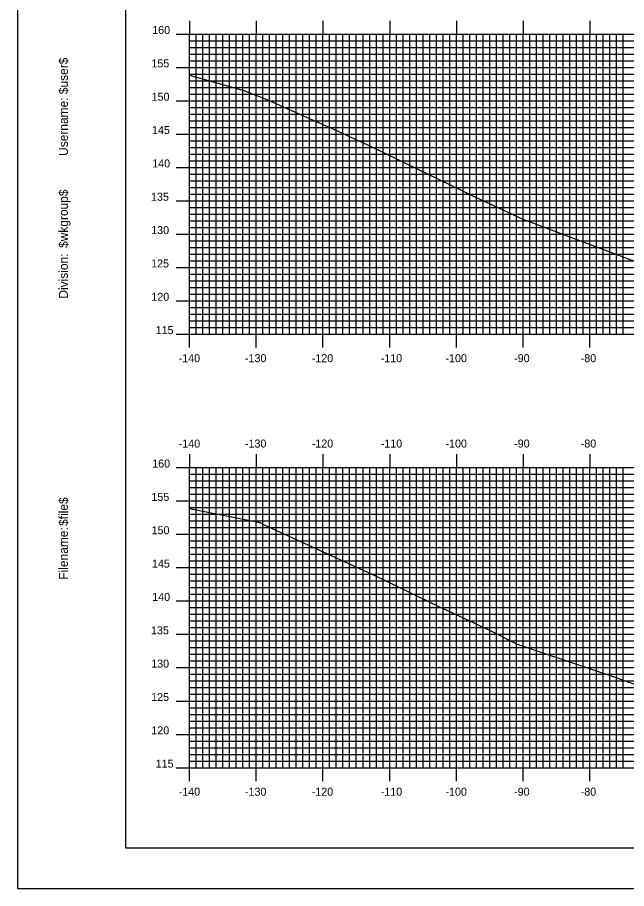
# Model space of a CAD drawing. Extents: x 851139 to 851482, y 366605 to 366825.
# Drawn here: x 851139.2 to 851230.4, y 366604.9 to 366735.5 of the extents above; entities that cross this region are included whole.
import ezdxf

# ---------------------------------------------------------------- set-up
doc = ezdxf.new("R2010")
doc.units = 0
for name, color, linetype in [('BORDER', 7, 'Continuous'), ('H_V ANNOTATION', 7, 'Continuous'), ('MAJOR', 7, 'Continuous'), ('MINOR', 7, 'Continuous'), ('PLOT BOUNDARY', 7, 'Continuous'), ('S_Roadway_Centerline', 7, 'Continuous')]:
    doc.layers.add(name, color=color, linetype=linetype)

msp = doc.modelspace()

# ---------------------------------------------------------------- linework, layer by layer
at = {"layer": 'BORDER'}
msp.add_lwpolyline([(851155.34, 366611.06), (851475.34, 366611.06), (851475.34, 366821.06), (851155.34, 366821.06)], close=True, dxfattribs=at)
at = {"layer": 'MAJOR'}
for p, q in [((851164.94, 366735.06), (851164.94, 366733.06)), ((851174.94, 366735.06), (851174.94, 366733.06)), ((851184.94, 366735.06), (851184.94, 366733.06)), ((851194.94, 366735.06), (851194.94, 366733.06)), ((851204.94, 366735.06), (851204.94, 366733.06)), ((851214.94, 366735.06), (851214.94, 366733.06)), ((851224.94, 366735.06), (851224.94, 366733.06)), ((851162.93, 366733.06), (851164.94, 366733.06)), ((851164.94, 366733.06), (851444.94, 366733.06)), ((851164.94, 366688.06), (851164.94, 366733.06)), ((851164.94, 366688.06), (851164.94, 366733.06)), ((851164.94, 366733.06), (851444.94, 366733.06)), ((851174.94, 366688.06), (851174.94, 366733.06)), ((851184.94, 366688.06), (851184.94, 366733.06)), ((851194.94, 366688.06), (851194.94, 366733.06)), ((851204.94, 366688.06), (851204.94, 366733.06)), ((851214.94, 366688.06), (851214.94, 366733.06)), ((851224.94, 366688.06), (851224.94, 366733.06)), ((851162.93, 366728.06), (851164.94, 366728.06)), ((851164.94, 366728.06), (851444.94, 366728.06)), ((851162.93, 366723.06), (851164.94, 366723.06)), ((851164.94, 366723.06), (851444.94, 366723.06)), ((851162.93, 366718.06), (851164.94, 366718.06)), ((851164.94, 366718.06), (851444.94, 366718.06)), ((851162.93, 366713.06), (851164.94, 366713.06)), ((851164.94, 366713.06), (851444.94, 366713.06)), ((851162.93, 366708.06), (851164.94, 366708.06)), ((851164.94, 366708.06), (851444.94, 366708.06)), ((851162.93, 366703.06), (851164.94, 366703.06)), ((851164.94, 366703.06), (851444.94, 366703.06)), ((851162.93, 366698.06), (851164.94, 366698.06)), ((851164.94, 366698.06), (851444.94, 366698.06)), ((851162.93, 366693.06), (851164.94, 366693.06)), ((851164.94, 366693.06), (851444.94, 366693.06)), ((851162.93, 366688.06), (851164.94, 366688.06)), ((851164.94, 366688.06), (851444.94, 366688.06)), ((851164.94, 366688.06), (851444.94, 366688.06)), ((851164.94, 366686.05), (851164.94, 366688.06)), ((851174.94, 366686.05), (851174.94, 366688.06)), ((851184.94, 366686.05), (851184.94, 366688.06)), ((851194.94, 366686.05), (851194.94, 366688.06)), ((851204.94, 366686.05), (851204.94, 366688.06)), ((851214.94, 366686.05), (851214.94, 366688.06)), ((851224.94, 366686.05), (851224.94, 366688.06)), ((851164.94, 366670.06), (851164.94, 366668.06)), ((851174.94, 366670.06), (851174.94, 366668.06)), ((851184.94, 366670.06), (851184.94, 366668.06)), ((851194.94, 366670.06), (851194.94, 366668.06)), ((851204.94, 366670.06), (851204.94, 366668.06)), ((851214.94, 366670.06), (851214.94, 366668.06)), ((851224.94, 366670.06), (851224.94, 366668.06)), ((851162.93, 366668.06), (851164.94, 366668.06)), ((851164.94, 366668.06), (851444.94, 366668.06)), ((851164.94, 366623.06), (851164.94, 366668.06)), ((851164.94, 366623.06), (851164.94, 366668.06)), ((851164.94, 366668.06), (851444.94, 366668.06)), ((851174.94, 366623.06), (851174.94, 366668.06)), ((851184.94, 366623.06), (851184.94, 366668.06)), ((851194.94, 366623.06), (851194.94, 366668.06)), ((851204.94, 366623.06), (851204.94, 366668.06)), ((851214.94, 366623.06), (851214.94, 366668.06)), ((851224.94, 366623.06), (851224.94, 366668.06)), ((851162.93, 366663.06), (851164.94, 366663.06)), ((851164.94, 366663.06), (851444.94, 366663.06)), ((851162.93, 366658.06), (851164.94, 366658.06)), ((851164.94, 366658.06), (851444.94, 366658.06)), ((851162.93, 366653.06), (851164.94, 366653.06)), ((851164.94, 366653.06), (851444.94, 366653.06)), ((851162.93, 366648.06), (851164.94, 366648.06)), ((851164.94, 366648.06), (851444.94, 366648.06)), ((851162.93, 366643.06), (851164.94, 366643.06)), ((851164.94, 366643.06), (851444.94, 366643.06)), ((851162.93, 366638.06), (851164.94, 366638.06)), ((851164.94, 366638.06), (851444.94, 366638.06)), ((851162.93, 366633.06), (851164.94, 366633.06)), ((851164.94, 366633.06), (851444.94, 366633.06)), ((851162.93, 366628.06), (851164.94, 366628.06)), ((851164.94, 366628.06), (851444.94, 366628.06)), ((851162.93, 366623.06), (851164.94, 366623.06)), ((851164.94, 366623.06), (851444.94, 366623.06)), ((851164.94, 366623.06), (851444.94, 366623.06)), ((851164.94, 366621.05), (851164.94, 366623.06)), ((851174.94, 366621.05), (851174.94, 366623.06)), ((851184.94, 366621.05), (851184.94, 366623.06)), ((851194.94, 366621.05), (851194.94, 366623.06)), ((851204.94, 366621.05), (851204.94, 366623.06)), ((851214.94, 366621.05), (851214.94, 366623.06)), ((851224.94, 366621.05), (851224.94, 366623.06))]:
    msp.add_line(p, q, dxfattribs=at)
at = {"layer": 'MINOR'}
for p, q in [((851165.94, 366688.06), (851165.94, 366733.06)), ((851166.94, 366688.06), (851166.94, 366733.06)), ((851167.94, 366688.06), (851167.94, 366733.06)), ((851168.94, 366688.06), (851168.94, 366733.06)), ((851169.94, 366688.06), (851169.94, 366733.06)), ((851170.94, 366688.06), (851170.94, 366733.06)), ((851171.94, 366688.06), (851171.94, 366733.06)), ((851172.94, 366688.06), (851172.94, 366733.06)), ((851173.94, 366688.06), (851173.94, 366733.06)), ((851175.94, 366688.06), (851175.94, 366733.06)), ((851176.94, 366688.06), (851176.94, 366733.06)), ((851177.94, 366688.06), (851177.94, 366733.06)), ((851178.94, 366688.06), (851178.94, 366733.06)), ((851179.94, 366688.06), (851179.94, 366733.06)), ((851180.94, 366688.06), (851180.94, 366733.06)), ((851181.94, 366688.06), (851181.94, 366733.06)), ((851182.94, 366688.06), (851182.94, 366733.06)), ((851183.94, 366688.06), (851183.94, 366733.06)), ((851185.94, 366688.06), (851185.94, 366733.06)), ((851186.94, 366688.06), (851186.94, 366733.06)), ((851187.94, 366688.06), (851187.94, 366733.06)), ((851188.94, 366688.06), (851188.94, 366733.06)), ((851189.94, 366688.06), (851189.94, 366733.06)), ((851190.94, 366688.06), (851190.94, 366733.06)), ((851191.94, 366688.06), (851191.94, 366733.06)), ((851192.94, 366688.06), (851192.94, 366733.06)), ((851193.94, 366688.06), (851193.94, 366733.06)), ((851195.94, 366688.06), (851195.94, 366733.06)), ((851196.94, 366688.06), (851196.94, 366733.06)), ((851197.94, 366688.06), (851197.94, 366733.06)), ((851198.94, 366688.06), (851198.94, 366733.06)), ((851199.94, 366688.06), (851199.94, 366733.06)), ((851200.94, 366688.06), (851200.94, 366733.06)), ((851201.94, 366688.06), (851201.94, 366733.06)), ((851202.94, 366688.06), (851202.94, 366733.06)), ((851203.94, 366688.06), (851203.94, 366733.06)), ((851205.94, 366688.06), (851205.94, 366733.06)), ((851206.94, 366688.06), (851206.94, 366733.06)), ((851207.94, 366688.06), (851207.94, 366733.06)), ((851208.94, 366688.06), (851208.94, 366733.06)), ((851209.94, 366688.06), (851209.94, 366733.06)), ((851210.94, 366688.06), (851210.94, 366733.06)), ((851211.94, 366688.06), (851211.94, 366733.06)), ((851212.94, 366688.06), (851212.94, 366733.06)), ((851213.94, 366688.06), (851213.94, 366733.06)), ((851215.94, 366688.06), (851215.94, 366733.06)), ((851216.94, 366688.06), (851216.94, 366733.06)), ((851217.94, 366688.06), (851217.94, 366733.06)), ((851218.94, 366688.06), (851218.94, 366733.06)), ((851219.94, 366688.06), (851219.94, 366733.06)), ((851220.94, 366688.06), (851220.94, 366733.06)), ((851221.94, 366688.06), (851221.94, 366733.06)), ((851222.94, 366688.06), (851222.94, 366733.06)), ((851223.94, 366688.06), (851223.94, 366733.06)), ((851225.94, 366688.06), (851225.94, 366733.06)), ((851226.94, 366688.06), (851226.94, 366733.06)), ((851227.94, 366688.06), (851227.94, 366733.06)), ((851228.94, 366688.06), (851228.94, 366733.06)), ((851229.94, 366688.06), (851229.94, 366733.06)), ((851164.94, 366732.06), (851444.94, 366732.06)), ((851164.94, 366732.06), (851166.94, 366732.06)), ((851164.94, 366731.06), (851444.94, 366731.06)), ((851164.94, 366731.06), (851166.94, 366731.06)), ((851164.94, 366730.06), (851444.94, 366730.06)), ((851164.94, 366730.06), (851166.94, 366730.06)), ((851164.94, 366729.06), (851444.94, 366729.06)), ((851164.94, 366729.06), (851166.94, 366729.06)), ((851164.94, 366727.06), (851444.94, 366727.06)), ((851164.94, 366727.06), (851166.94, 366727.06)), ((851164.94, 366726.06), (851444.94, 366726.06)), ((851164.94, 366726.06), (851166.94, 366726.06)), ((851164.94, 366725.06), (851444.94, 366725.06)), ((851164.94, 366725.06), (851166.94, 366725.06)), ((851164.94, 366724.06), (851444.94, 366724.06)), ((851164.94, 366724.06), (851166.94, 366724.06)), ((851164.94, 366722.06), (851444.94, 366722.06)), ((851164.94, 366722.06), (851166.94, 366722.06)), ((851164.94, 366721.06), (851444.94, 366721.06)), ((851164.94, 366721.06), (851166.94, 366721.06)), ((851164.94, 366720.06), (851444.94, 366720.06)), ((851164.94, 366720.06), (851166.94, 366720.06)), ((851164.94, 366719.06), (851444.94, 366719.06)), ((851164.94, 366719.06), (851166.94, 366719.06)), ((851164.94, 366717.06), (851444.94, 366717.06)), ((851164.94, 366717.06), (851166.94, 366717.06)), ((851164.94, 366716.06), (851444.94, 366716.06)), ((851164.94, 366716.06), (851166.94, 366716.06)), ((851164.94, 366715.06), (851444.94, 366715.06)), ((851164.94, 366715.06), (851166.94, 366715.06)), ((851164.94, 366714.06), (851444.94, 366714.06)), ((851164.94, 366714.06), (851166.94, 366714.06)), ((851164.94, 366712.06), (851444.94, 366712.06)), ((851164.94, 366712.06), (851166.94, 366712.06)), ((851164.94, 366711.06), (851444.94, 366711.06)), ((851164.94, 366711.06), (851166.94, 366711.06)), ((851164.94, 366710.06), (851444.94, 366710.06)), ((851164.94, 366710.06), (851166.94, 366710.06)), ((851164.94, 366709.06), (851444.94, 366709.06)), ((851164.94, 366709.06), (851166.94, 366709.06)), ((851164.94, 366707.06), (851444.94, 366707.06)), ((851164.94, 366707.06), (851166.94, 366707.06)), ((851164.94, 366706.06), (851444.94, 366706.06)), ((851164.94, 366706.06), (851166.94, 366706.06)), ((851164.94, 366705.06), (851444.94, 366705.06)), ((851164.94, 366705.06), (851166.94, 366705.06)), ((851164.94, 366704.06), (851444.94, 366704.06)), ((851164.94, 366704.06), (851166.94, 366704.06)), ((851164.94, 366702.06), (851444.94, 366702.06)), ((851164.94, 366702.06), (851166.94, 366702.06)), ((851164.94, 366701.06), (851444.94, 366701.06)), ((851164.94, 366701.06), (851166.94, 366701.06)), ((851164.94, 366700.06), (851444.94, 366700.06)), ((851164.94, 366700.06), (851166.94, 366700.06)), ((851164.94, 366699.06), (851444.94, 366699.06)), ((851164.94, 366699.06), (851166.94, 366699.06)), ((851164.94, 366697.06), (851444.94, 366697.06)), ((851164.94, 366697.06), (851166.94, 366697.06)), ((851164.94, 366696.06), (851444.94, 366696.06)), ((851164.94, 366696.06), (851166.94, 366696.06)), ((851164.94, 366695.06), (851444.94, 366695.06)), ((851164.94, 366695.06), (851166.94, 366695.06)), ((851164.94, 366694.06), (851444.94, 366694.06)), ((851164.94, 366694.06), (851166.94, 366694.06)), ((851164.94, 366692.06), (851444.94, 366692.06)), ((851164.94, 366692.06), (851166.94, 366692.06)), ((851164.94, 366691.06), (851444.94, 366691.06)), ((851164.94, 366691.06), (851166.94, 366691.06)), ((851164.94, 366690.06), (851444.94, 366690.06)), ((851164.94, 366690.06), (851166.94, 366690.06)), ((851164.94, 366689.06), (851444.94, 366689.06)), ((851164.94, 366689.06), (851166.94, 366689.06)), ((851165.94, 366623.06), (851165.94, 366668.06)), ((851166.94, 366623.06), (851166.94, 366668.06)), ((851167.94, 366623.06), (851167.94, 366668.06)), ((851168.94, 366623.06), (851168.94, 366668.06)), ((851169.94, 366623.06), (851169.94, 366668.06)), ((851170.94, 366623.06), (851170.94, 366668.06)), ((851171.94, 366623.06), (851171.94, 366668.06)), ((851172.94, 366623.06), (851172.94, 366668.06)), ((851173.94, 366623.06), (851173.94, 366668.06)), ((851175.94, 366623.06), (851175.94, 366668.06)), ((851176.94, 366623.06), (851176.94, 366668.06)), ((851177.94, 366623.06), (851177.94, 366668.06)), ((851178.94, 366623.06), (851178.94, 366668.06)), ((851179.94, 366623.06), (851179.94, 366668.06)), ((851180.94, 366623.06), (851180.94, 366668.06)), ((851181.94, 366623.06), (851181.94, 366668.06)), ((851182.94, 366623.06), (851182.94, 366668.06)), ((851183.94, 366623.06), (851183.94, 366668.06)), ((851185.94, 366623.06), (851185.94, 366668.06)), ((851186.94, 366623.06), (851186.94, 366668.06)), ((851187.94, 366623.06), (851187.94, 366668.06)), ((851188.94, 366623.06), (851188.94, 366668.06)), ((851189.94, 366623.06), (851189.94, 366668.06)), ((851190.94, 366623.06), (851190.94, 366668.06)), ((851191.94, 366623.06), (851191.94, 366668.06)), ((851192.94, 366623.06), (851192.94, 366668.06)), ((851193.94, 366623.06), (851193.94, 366668.06)), ((851195.94, 366623.06), (851195.94, 366668.06)), ((851196.94, 366623.06), (851196.94, 366668.06)), ((851197.94, 366623.06), (851197.94, 366668.06)), ((851198.94, 366623.06), (851198.94, 366668.06)), ((851199.94, 366623.06), (851199.94, 366668.06)), ((851200.94, 366623.06), (851200.94, 366668.06)), ((851201.94, 366623.06), (851201.94, 366668.06)), ((851202.94, 366623.06), (851202.94, 366668.06)), ((851203.94, 366623.06), (851203.94, 366668.06)), ((851205.94, 366623.06), (851205.94, 366668.06)), ((851206.94, 366623.06), (851206.94, 366668.06)), ((851207.94, 366623.06), (851207.94, 366668.06)), ((851208.94, 366623.06), (851208.94, 366668.06)), ((851209.94, 366623.06), (851209.94, 366668.06)), ((851210.94, 366623.06), (851210.94, 366668.06)), ((851211.94, 366623.06), (851211.94, 366668.06)), ((851212.94, 366623.06), (851212.94, 366668.06)), ((851213.94, 366623.06), (851213.94, 366668.06)), ((851215.94, 366623.06), (851215.94, 366668.06)), ((851216.94, 366623.06), (851216.94, 366668.06)), ((851217.94, 366623.06), (851217.94, 366668.06)), ((851218.94, 366623.06), (851218.94, 366668.06)), ((851219.94, 366623.06), (851219.94, 366668.06)), ((851220.94, 366623.06), (851220.94, 366668.06)), ((851221.94, 366623.06), (851221.94, 366668.06)), ((851222.94, 366623.06), (851222.94, 366668.06)), ((851223.94, 366623.06), (851223.94, 366668.06)), ((851225.94, 366623.06), (851225.94, 366668.06)), ((851226.94, 366623.06), (851226.94, 366668.06)), ((851227.94, 366623.06), (851227.94, 366668.06)), ((851228.94, 366623.06), (851228.94, 366668.06)), ((851229.94, 366623.06), (851229.94, 366668.06)), ((851164.94, 366667.06), (851444.94, 366667.06)), ((851164.94, 366667.06), (851166.94, 366667.06)), ((851164.94, 366666.06), (851444.94, 366666.06)), ((851164.94, 366666.06), (851166.94, 366666.06)), ((851164.94, 366665.06), (851444.94, 366665.06)), ((851164.94, 366665.06), (851166.94, 366665.06)), ((851164.94, 366664.06), (851444.94, 366664.06)), ((851164.94, 366664.06), (851166.94, 366664.06)), ((851164.94, 366662.06), (851444.94, 366662.06)), ((851164.94, 366662.06), (851166.94, 366662.06)), ((851164.94, 366661.06), (851444.94, 366661.06)), ((851164.94, 366661.06), (851166.94, 366661.06)), ((851164.94, 366660.06), (851444.94, 366660.06)), ((851164.94, 366660.06), (851166.94, 366660.06)), ((851164.94, 366659.06), (851444.94, 366659.06)), ((851164.94, 366659.06), (851166.94, 366659.06)), ((851164.94, 366657.06), (851444.94, 366657.06)), ((851164.94, 366657.06), (851166.94, 366657.06)), ((851164.94, 366656.06), (851444.94, 366656.06)), ((851164.94, 366656.06), (851166.94, 366656.06)), ((851164.94, 366655.06), (851444.94, 366655.06)), ((851164.94, 366655.06), (851166.94, 366655.06)), ((851164.94, 366654.06), (851444.94, 366654.06)), ((851164.94, 366654.06), (851166.94, 366654.06)), ((851164.94, 366652.06), (851444.94, 366652.06)), ((851164.94, 366652.06), (851166.94, 366652.06)), ((851164.94, 366651.06), (851444.94, 366651.06)), ((851164.94, 366651.06), (851166.94, 366651.06)), ((851164.94, 366650.06), (851444.94, 366650.06)), ((851164.94, 366650.06), (851166.94, 366650.06)), ((851164.94, 366649.06), (851444.94, 366649.06)), ((851164.94, 366649.06), (851166.94, 366649.06)), ((851164.94, 366647.06), (851444.94, 366647.06)), ((851164.94, 366647.06), (851166.94, 366647.06)), ((851164.94, 366646.06), (851444.94, 366646.06)), ((851164.94, 366646.06), (851166.94, 366646.06)), ((851164.94, 366645.06), (851444.94, 366645.06)), ((851164.94, 366645.06), (851166.94, 366645.06)), ((851164.94, 366644.06), (851444.94, 366644.06)), ((851164.94, 366644.06), (851166.94, 366644.06)), ((851164.94, 366642.06), (851444.94, 366642.06)), ((851164.94, 366642.06), (851166.94, 366642.06)), ((851164.94, 366641.06), (851444.94, 366641.06)), ((851164.94, 366641.06), (851166.94, 366641.06)), ((851164.94, 366640.06), (851444.94, 366640.06)), ((851164.94, 366640.06), (851166.94, 366640.06)), ((851164.94, 366639.06), (851444.94, 366639.06)), ((851164.94, 366639.06), (851166.94, 366639.06)), ((851164.94, 366637.06), (851444.94, 366637.06)), ((851164.94, 366637.06), (851166.94, 366637.06)), ((851164.94, 366636.06), (851444.94, 366636.06)), ((851164.94, 366636.06), (851166.94, 366636.06)), ((851164.94, 366635.06), (851444.94, 366635.06)), ((851164.94, 366635.06), (851166.94, 366635.06)), ((851164.94, 366634.06), (851444.94, 366634.06)), ((851164.94, 366634.06), (851166.94, 366634.06)), ((851164.94, 366632.06), (851444.94, 366632.06)), ((851164.94, 366632.06), (851166.94, 366632.06)), ((851164.94, 366631.06), (851444.94, 366631.06)), ((851164.94, 366631.06), (851166.94, 366631.06)), ((851164.94, 366630.06), (851444.94, 366630.06)), ((851164.94, 366630.06), (851166.94, 366630.06)), ((851164.94, 366629.06), (851444.94, 366629.06)), ((851164.94, 366629.06), (851166.94, 366629.06)), ((851164.94, 366627.06), (851444.94, 366627.06)), ((851164.94, 366627.06), (851166.94, 366627.06)), ((851164.94, 366626.06), (851444.94, 366626.06)), ((851164.94, 366626.06), (851166.94, 366626.06)), ((851164.94, 366625.06), (851444.94, 366625.06)), ((851164.94, 366625.06), (851166.94, 366625.06)), ((851164.94, 366624.06), (851444.94, 366624.06)), ((851164.94, 366624.06), (851166.94, 366624.06))]:
    msp.add_line(p, q, dxfattribs=at)
at = {"layer": 'PLOT BOUNDARY'}
msp.add_lwpolyline([(851139.15, 366604.94), (851479.15, 366604.94), (851479.15, 366824.94), (851139.15, 366824.94)], close=True, dxfattribs=at)
at = {"layer": 'S_Roadway_Centerline'}
for points in [[(851164.94, 366726.88), (851173.09, 366724.59), (851176.28, 366723.32), (851186.53, 366718.78), (851190.31, 366717.05), (851192.24, 366716.14), (851207.49, 366708.77), (851214.89, 366705.3), (851231.46, 366699.05)], [(851164.94, 366661.93), (851174.23, 366660.05), (851175.26, 366659.86), (851175.58, 366659.75), (851176.13, 366659.49), (851192.79, 366651.82), (851202.18, 366647.29), (851210.02, 366643.62), (851214.05, 366641.6), (851228.13, 366636.82), (851240.53, 366632.37)]]:
    msp.add_lwpolyline(points, dxfattribs=at)

# ---------------------------------------------------------------- texts
at = {"layer": 'BORDER'}
for s, p in [('$user$', (851146.71, 366724.04)), ('Username:', (851146.71, 366714.79)), ('$wkgroup$', (851146.71, 366700.99)), ('Division:', (851146.71, 366693.39)), ('$file$', (851146.71, 366659.31)), ('Filename:', (851146.71, 366651.25))]:
    msp.add_text(s, height=1.339, rotation=90, dxfattribs=at).set_placement(p)
at = {"layer": 'H_V ANNOTATION'}
for s, p in [('160', (851159.35, 366733.06)), ('155', (851159.23, 366728.06)), ('150', (851159.26, 366723.06)), ('145', (851159.32, 366718.06)), ('140', (851159.35, 366713.06)), ('135', (851159.17, 366708.06)), ('130', (851159.2, 366703.06)), ('125', (851159.19, 366698.06)), ('120', (851159.22, 366693.06)), ('115', (851159.87, 366688.06)), ('-140', (851163.32, 366683.86)), ('-130', (851173.25, 366683.86)), ('-120', (851183.26, 366683.86)), ('-110', (851193.6, 366683.86)), ('-100', (851203.3, 366683.86)), ('-90', (851213.59, 366683.86)), ('-80', (851223.57, 366683.86)), ('-140', (851163.32, 366671.06)), ('-130', (851173.25, 366671.06)), ('-120', (851183.26, 366671.06)), ('-110', (851193.6, 366671.06)), ('-100', (851203.3, 366671.06)), ('-90', (851213.59, 366671.06)), ('-80', (851223.57, 366671.06)), ('160', (851159.35, 366668.06)), ('155', (851159.23, 366663.06)), ('150', (851159.26, 366658.06)), ('145', (851159.32, 366653.06)), ('140', (851159.35, 366648.06)), ('135', (851159.17, 366643.06)), ('130', (851159.2, 366638.06)), ('125', (851159.19, 366633.06)), ('120', (851159.22, 366628.06)), ('115', (851159.87, 366623.06)), ('-140', (851163.32, 366618.86)), ('-130', (851173.25, 366618.86)), ('-120', (851183.26, 366618.86)), ('-110', (851193.6, 366618.86)), ('-100', (851203.3, 366618.86)), ('-90', (851213.59, 366618.86)), ('-80', (851223.57, 366618.86))]:
    msp.add_text(s, height=1.2, dxfattribs=at).set_placement(p)
at = {"layer": 'MAJOR'}
for p in [(851164.93, 366688.06), (851164.93, 366623.06)]:
    msp.add_text('-', height=0.012, dxfattribs=at).set_placement(p)

doc.saveas('drawing.dxf')
